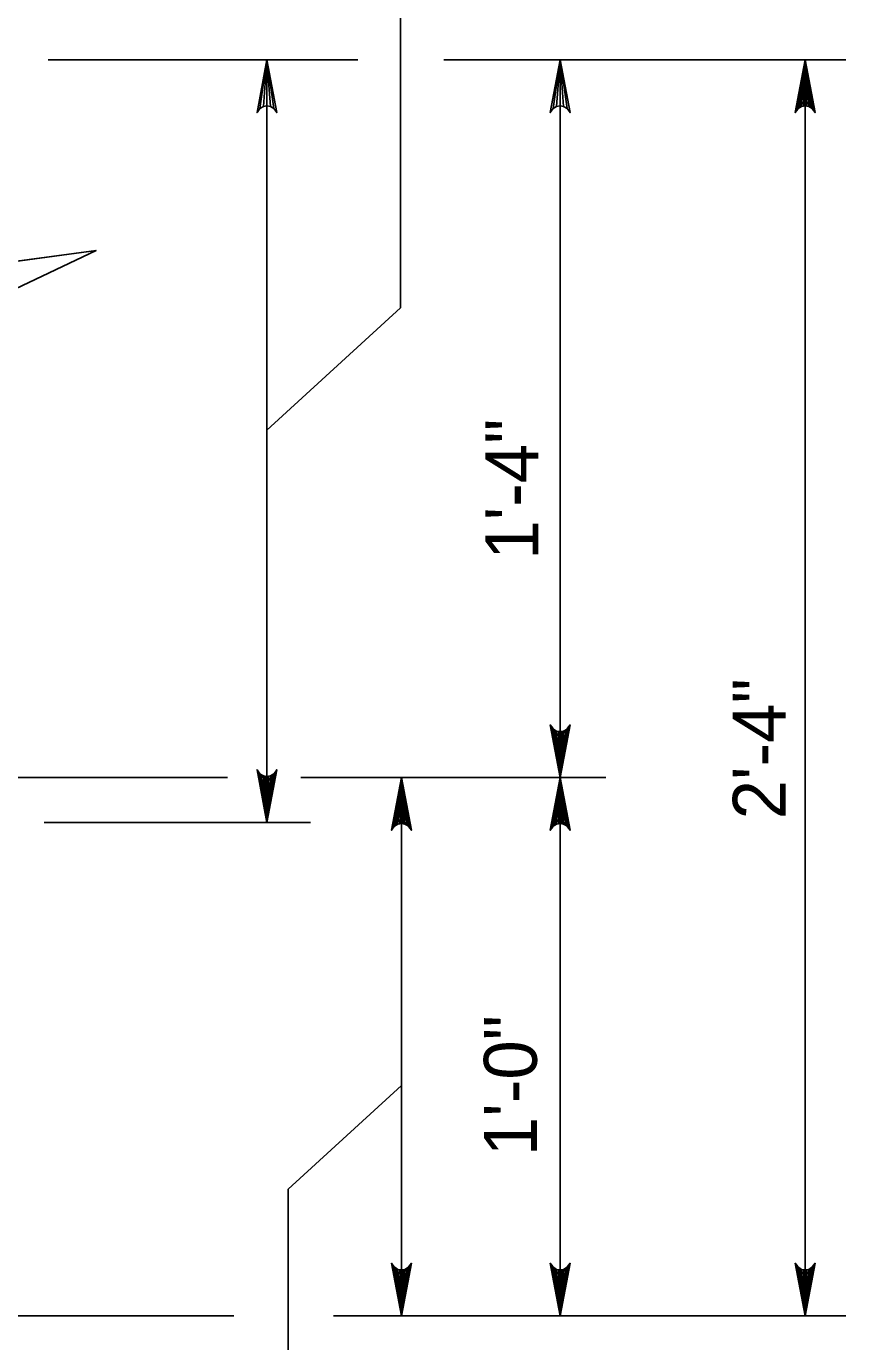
# Model space of a CAD drawing. Extents: x 638079 to 640019, y 297691 to 298879.
# Drawn here: x 639494.4 to 639540.8, y 298729 to 298803.5 of the extents above; entities that cross this region are included whole.
import ezdxf

# ---------------------------------------------------------------- set-up
doc = ezdxf.new("R2010")
doc.units = 0
doc.layers.add('1', color=7, linetype='Continuous')

msp = doc.modelspace()

# ---------------------------------------------------------------- linework, layer by layer
at = {"layer": '1'}
for p, q in [((639515.637, 298787.525), (639515.637, 298830.816)), ((639495.684, 298801.575), (639513.209, 298801.575)), ((639508.064, 298758.394), (639508.064, 298801.575)), ((639518.084, 298801.575), (639540.839, 298801.575)), ((639524.669, 298760.936), (639524.669, 298801.575)), ((639538.544, 298730.456), (639538.544, 298801.575)), ((639515.637, 298787.525), (639508.064, 298780.616)), ((639421.456, 298760.936), (639505.834, 298760.936)), ((639509.995, 298760.936), (639527.251, 298760.936)), ((639515.684, 298730.456), (639515.684, 298760.936)), ((639524.669, 298730.456), (639524.669, 298760.936)), ((639495.45, 298758.394), (639510.538, 298758.394)), ((639509.263, 298737.641), (639515.684, 298743.5)), ((639509.263, 298685.764), (639509.263, 298737.641)), ((639421.456, 298730.456), (639506.188, 298730.456)), ((639511.844, 298730.456), (639540.839, 298730.456))]:
    msp.add_line(p, q, dxfattribs=at)
msp.add_lwpolyline([(639488.261, 298789.413), (639493.433, 298791.946), (639493.433, 298801.575), (639342.891, 298801.575), (639342.891, 298799.67), (639341.94, 298799.67), (639341.94, 298760.936), (639418.14, 298760.936), (639438.458, 298781.254), (639493.433, 298781.254), (639493.433, 298788.428), (639498.394, 298790.783)], close=True, dxfattribs=at)
for points in [[(639508.064, 298801.575), (639508.624, 298798.592), (639508.464, 298798.822), (639508.264, 298798.941), (639508.064, 298798.975), (639507.864, 298798.941), (639507.664, 298798.822), (639507.505, 298798.592), (639508.064, 298801.575), (639507.664, 298798.822), (639507.864, 298798.941), (639508.064, 298801.575), (639508.064, 298798.975), (639508.264, 298798.941), (639508.064, 298801.575), (639508.464, 298798.822)], [(639524.669, 298801.575), (639525.229, 298798.592), (639525.069, 298798.822), (639524.869, 298798.941), (639524.669, 298798.975), (639524.469, 298798.941), (639524.269, 298798.822), (639524.11, 298798.592), (639524.669, 298801.575), (639524.269, 298798.822), (639524.469, 298798.941), (639524.669, 298801.575), (639524.669, 298798.975), (639524.869, 298798.941), (639524.669, 298801.575), (639525.069, 298798.822)], [(639538.544, 298801.575), (639539.104, 298798.592), (639539.024, 298798.707), (639538.944, 298798.822), (639538.844, 298798.881), (639538.744, 298798.941), (639538.644, 298798.958), (639538.544, 298798.975), (639538.444, 298798.958), (639538.344, 298798.941), (639538.244, 298798.881), (639538.144, 298798.822), (639538.065, 298798.707), (639537.985, 298798.592), (639538.544, 298801.575), (639538.065, 298798.707), (639538.144, 298798.822), (639538.544, 298801.575), (639538.244, 298798.881), (639538.344, 298798.941), (639538.544, 298801.575), (639538.444, 298798.958), (639538.544, 298798.975), (639538.544, 298801.575), (639538.644, 298798.958), (639538.744, 298798.941), (639538.544, 298801.575), (639538.844, 298798.881), (639538.944, 298798.822), (639538.544, 298801.575), (639539.024, 298798.707)], [(639493.433, 298791.946), (639488.248, 298789.409), (639498.397, 298790.789), (639493.433, 298788.428)], [(639524.669, 298760.936), (639524.11, 298763.919), (639524.19, 298763.804), (639524.269, 298763.689), (639524.369, 298763.63), (639524.469, 298763.57), (639524.569, 298763.553), (639524.669, 298763.536), (639524.769, 298763.553), (639524.869, 298763.57), (639524.969, 298763.63), (639525.069, 298763.689), (639525.149, 298763.804), (639525.229, 298763.919), (639524.669, 298760.936), (639525.149, 298763.804), (639525.069, 298763.689), (639524.669, 298760.936), (639524.969, 298763.63), (639524.869, 298763.57), (639524.669, 298760.936), (639524.769, 298763.553), (639524.669, 298763.536), (639524.669, 298760.936), (639524.569, 298763.553), (639524.469, 298763.57), (639524.669, 298760.936), (639524.369, 298763.63), (639524.269, 298763.689), (639524.669, 298760.936), (639524.19, 298763.804)], [(639508.064, 298758.394), (639507.505, 298761.377), (639507.585, 298761.262), (639507.664, 298761.147), (639507.764, 298761.088), (639507.864, 298761.028), (639507.964, 298761.011), (639508.064, 298760.994), (639508.164, 298761.011), (639508.264, 298761.028), (639508.364, 298761.088), (639508.464, 298761.147), (639508.544, 298761.262), (639508.624, 298761.377), (639508.064, 298758.394), (639508.544, 298761.262), (639508.464, 298761.147), (639508.064, 298758.394), (639508.364, 298761.088), (639508.264, 298761.028), (639508.064, 298758.394), (639508.164, 298761.011), (639508.064, 298760.994), (639508.064, 298758.394), (639507.964, 298761.011), (639507.864, 298761.028), (639508.064, 298758.394), (639507.764, 298761.088), (639507.664, 298761.147), (639508.064, 298758.394), (639507.585, 298761.262)], [(639515.684, 298760.936), (639516.244, 298757.953), (639516.164, 298758.068), (639516.084, 298758.183), (639515.984, 298758.242), (639515.884, 298758.302), (639515.784, 298758.319), (639515.684, 298758.336), (639515.584, 298758.319), (639515.484, 298758.302), (639515.384, 298758.242), (639515.284, 298758.183), (639515.205, 298758.068), (639515.125, 298757.953), (639515.684, 298760.936), (639515.205, 298758.068), (639515.284, 298758.183), (639515.684, 298760.936), (639515.384, 298758.242), (639515.484, 298758.302), (639515.684, 298760.936), (639515.584, 298758.319), (639515.684, 298758.336), (639515.684, 298760.936), (639515.784, 298758.319), (639515.884, 298758.302), (639515.684, 298760.936), (639515.984, 298758.242), (639516.084, 298758.183), (639515.684, 298760.936), (639516.164, 298758.068)], [(639524.669, 298760.936), (639525.229, 298757.953), (639525.149, 298758.068), (639525.069, 298758.183), (639524.969, 298758.242), (639524.869, 298758.302), (639524.769, 298758.319), (639524.669, 298758.336), (639524.569, 298758.319), (639524.469, 298758.302), (639524.369, 298758.242), (639524.269, 298758.183), (639524.19, 298758.068), (639524.11, 298757.953), (639524.669, 298760.936), (639524.19, 298758.068), (639524.269, 298758.183), (639524.669, 298760.936), (639524.369, 298758.242), (639524.469, 298758.302), (639524.669, 298760.936), (639524.569, 298758.319), (639524.669, 298758.336), (639524.669, 298760.936), (639524.769, 298758.319), (639524.869, 298758.302), (639524.669, 298760.936), (639524.969, 298758.242), (639525.069, 298758.183), (639524.669, 298760.936), (639525.149, 298758.068)], [(639515.684, 298730.456), (639515.125, 298733.439), (639515.205, 298733.324), (639515.284, 298733.209), (639515.384, 298733.15), (639515.484, 298733.09), (639515.584, 298733.073), (639515.684, 298733.056), (639515.784, 298733.073), (639515.884, 298733.09), (639515.984, 298733.15), (639516.084, 298733.209), (639516.164, 298733.324), (639516.244, 298733.439), (639515.684, 298730.456), (639516.164, 298733.324), (639516.084, 298733.209), (639515.684, 298730.456), (639515.984, 298733.15), (639515.884, 298733.09), (639515.684, 298730.456), (639515.784, 298733.073), (639515.684, 298733.056), (639515.684, 298730.456), (639515.584, 298733.073), (639515.484, 298733.09), (639515.684, 298730.456), (639515.384, 298733.15), (639515.284, 298733.209), (639515.684, 298730.456), (639515.205, 298733.324)], [(639524.669, 298730.456), (639524.11, 298733.439), (639524.19, 298733.324), (639524.269, 298733.209), (639524.369, 298733.15), (639524.469, 298733.09), (639524.569, 298733.073), (639524.669, 298733.056), (639524.769, 298733.073), (639524.869, 298733.09), (639524.969, 298733.15), (639525.069, 298733.209), (639525.149, 298733.324), (639525.229, 298733.439), (639524.669, 298730.456), (639525.149, 298733.324), (639525.069, 298733.209), (639524.669, 298730.456), (639524.969, 298733.15), (639524.869, 298733.09), (639524.669, 298730.456), (639524.769, 298733.073), (639524.669, 298733.056), (639524.669, 298730.456), (639524.569, 298733.073), (639524.469, 298733.09), (639524.669, 298730.456), (639524.369, 298733.15), (639524.269, 298733.209), (639524.669, 298730.456), (639524.19, 298733.324)], [(639538.544, 298730.456), (639537.985, 298733.439), (639538.065, 298733.324), (639538.144, 298733.209), (639538.244, 298733.15), (639538.344, 298733.09), (639538.444, 298733.073), (639538.544, 298733.056), (639538.644, 298733.073), (639538.744, 298733.09), (639538.844, 298733.15), (639538.944, 298733.209), (639539.024, 298733.324), (639539.104, 298733.439), (639538.544, 298730.456), (639539.024, 298733.324), (639538.944, 298733.209), (639538.544, 298730.456), (639538.844, 298733.15), (639538.744, 298733.09), (639538.544, 298730.456), (639538.644, 298733.073), (639538.544, 298733.056), (639538.544, 298730.456), (639538.444, 298733.073), (639538.344, 298733.09), (639538.544, 298730.456), (639538.244, 298733.15), (639538.144, 298733.209), (639538.544, 298730.456), (639538.065, 298733.324)]]:
    msp.add_lwpolyline(points, dxfattribs=at)

# ---------------------------------------------------------------- texts
for s, p in [('1\'-4"', (639523.432, 298773.27)), ('2\'-4"', (639537.446, 298758.57)), ('1\'-0"', (639523.35, 298739.499))]:
    msp.add_text(s, height=3, rotation=90, dxfattribs=at).set_placement(p)

doc.saveas('drawing.dxf')
